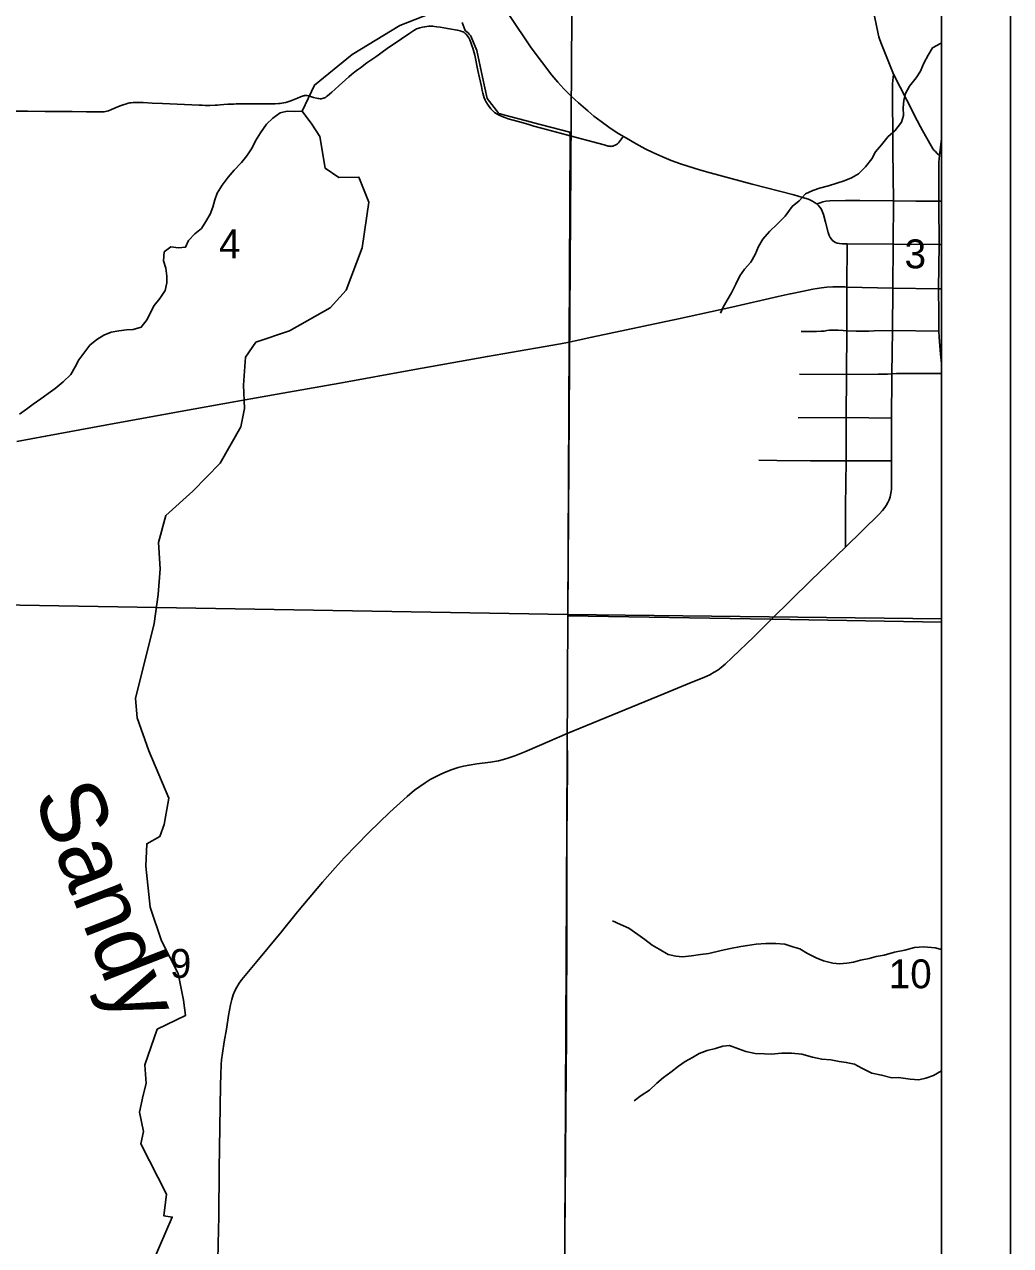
# Model space of a CAD drawing. Extents: x -8.8 to 41.4, y 0 to 34.6.
# Drawn here: x -3.204 to -1.774, y 16.599 to 18.37 of the extents above; entities that cross this region are included whole.
import ezdxf

# ---------------------------------------------------------------- set-up
doc = ezdxf.new("R2010")
doc.units = 0
for name, color, linetype in [('GM_X_City_Street', 7, 'Continuous'), ('GM_X_Corporation', 7, 'Continuous'), ('GM_X_County_Road', 7, 'Continuous'), ('GM_X_Minor_River', 7, 'Continuous'), ('GM_X_Minor_River_Text', 7, 'Continuous'), ('GM_X_State_Route', 7, 'Continuous'), ('GM_X_Township_Road', 7, 'Continuous'), ('GM_X_Township_Text', 7, 'Continuous'), ('SH_Border', 7, 'Continuous')]:
    doc.layers.add(name, color=color, linetype=linetype)

msp = doc.modelspace()

# ---------------------------------------------------------------- linework, layer by layer
at = {"layer": 'GM_X_City_Street'}
for p, q in [((-1.878, 18.0513), (-1.8743, 18.0512)), ((-1.9457, 17.9263), (-1.8782, 17.9255))]:
    msp.add_line(p, q, dxfattribs=at)
for points in [[(-1.8773, 18.1802), (-1.881, 18.1837), (-1.8833, 18.1858), (-1.8854, 18.1881), (-1.8876, 18.191), (-1.8895, 18.194), (-1.902, 18.2163), (-1.9048, 18.2218), (-1.9098, 18.2311), (-1.9245, 18.2605), (-1.9441, 18.298)], [(-2.0551, 18.11), (-2.0517, 18.1112), (-2.0489, 18.1122), (-2.0465, 18.1129), (-2.0422, 18.1137), (-2.0366, 18.1143), (-2.0138, 18.1148), (-1.9928, 18.1151), (-1.9442, 18.1144)], [(-1.9442, 18.1144), (-1.9115, 18.114), (-1.8784, 18.1138), (-1.8743, 18.1137)], [(-2.0136, 17.6123), (-2.0137, 17.6716), (-2.0129, 17.7375), (-2.0125, 17.8002), (-2.012, 17.8627), (-2.0117, 17.926), (-2.0117, 17.9894), (-2.0111, 18.0522)], [(-2.0779, 17.9249), (-2.0556, 17.9251), (-2.0488, 17.9252), (-2.0445, 17.9256), (-2.0408, 17.9261), (-2.0369, 17.9267), (-2.0323, 17.927), (-2.0242, 17.9267), (-2.0169, 17.9263), (-2.0117, 17.926), (-1.9983, 17.9253), (-1.9865, 17.9252), (-1.9797, 17.9254), (-1.9723, 17.9258), (-1.9457, 17.9263)], [(-2.0802, 17.8631), (-2.012, 17.8627), (-1.9662, 17.863), (-1.9526, 17.8632), (-1.9464, 17.8636)], [(-1.9464, 17.8636), (-1.9397, 17.8641), (-1.9302, 17.8642), (-1.8743, 17.8638)], [(-2.0824, 17.7998), (-2.0125, 17.8002), (-1.947, 17.7993)], [(-2.1395, 17.7383), (-2.1134, 17.7377), (-2.0644, 17.7374), (-2.0129, 17.7375), (-1.9469, 17.7373)]]:
    msp.add_lwpolyline(points, dxfattribs=at)
at = {"layer": 'GM_X_Corporation'}
for points in [[(-5.4008, 18.6369), (-5.4129, 17.3836), (-5.4212, 16.5483), (-5.4282, 16.3507), (-5.435, 15.3164), (-5.4368, 15.0446), (-5.4404, 14.5882), (-5.4429, 14.2618), (-5.4432, 14.2265), (-5.4442, 14.1), (-1.8743, 14.1), (-1.8743, 18.5906)], [(-2.5697, 18.3731), (-2.565, 18.3613), (-2.5643, 18.3608), (-2.564, 18.3606), (-2.561, 18.3581), (-2.5608, 18.3579), (-2.5592, 18.3561), (-2.5578, 18.3545), (-2.5576, 18.3542), (-2.5563, 18.3522), (-2.5484, 18.3325), (-2.5399, 18.2938), (-2.5331, 18.2626), (-2.5162, 18.241), (-2.5002, 18.2367), (-2.4874, 18.2334), (-2.469, 18.2285), (-2.4674, 18.2281), (-2.4134, 18.2139), (-2.4131, 18.2093), (-2.4144, 17.9101), (-2.4164, 17.5126), (-2.1219, 17.5076), (-1.8743, 17.5032), (-1.8743, 18.5904)]]:
    msp.add_lwpolyline(points, dxfattribs=at)
for points in [[(-3.3893, 18.614), (-2.4092, 18.5999), (-2.4162, 17.5144), (-3.4102, 17.5315)], [(-1.8743, 17.5082), (-1.8743, 18.5922), (-2.4092, 18.5999), (-2.4162, 17.5144)], [(-2.4162, 17.5144), (-2.421, 16.5107), (-3.4233, 16.5283), (-3.4102, 17.5315)], [(-1.8743, 16.504), (-1.8743, 17.5082), (-2.4162, 17.5144), (-2.421, 16.5107)]]:
    msp.add_lwpolyline(points, close=True, dxfattribs=at)
at = {"layer": 'GM_X_County_Road'}
for p, q in [((-1.8773, 18.1802), (-1.8743, 18.2044)), ((-1.878, 18.0513), (-1.8784, 18.1098))]:
    msp.add_line(p, q, dxfattribs=at)
msp.add_lwpolyline([(-1.8784, 18.1098), (-1.8784, 18.1138), (-1.8782, 18.1706), (-1.8778, 18.1755), (-1.8773, 18.1802)], dxfattribs=at)
at = {"layer": 'GM_X_Minor_River'}
for points in [[(-3.027, 16.5553), (-2.9899, 16.6404), (-3.0023, 16.6424), (-2.9985, 16.6738), (-3.0354, 16.7467), (-3.0317, 16.7645), (-3.0372, 16.7924), (-3.0321, 16.8174), (-3.0278, 16.834), (-3.0295, 16.8614), (-3.0117, 16.9129), (-2.9709, 16.9328), (-2.9735, 16.955), (-2.9816, 16.9937), (-3.0057, 17.041), (-3.0222, 17.0899), (-3.0281, 17.1495), (-3.0269, 17.1818), (-3.008, 17.1922), (-3.0017, 17.2098), (-2.995, 17.248), (-3.0241, 17.3169), (-3.0406, 17.3646), (-3.0434, 17.3925), (-3.0164, 17.5016), (-3.0104, 17.5436), (-3.0076, 17.5808), (-3.01, 17.6189), (-2.9992, 17.6578), (-2.9601, 17.6933), (-2.9203, 17.7341), (-2.8904, 17.7867), (-2.8853, 17.8131), (-2.8868, 17.847), (-2.8839, 17.8877), (-2.8687, 17.9092), (-2.82, 17.9257), (-2.7608, 17.959), (-2.7379, 17.9848), (-2.7146, 18.046), (-2.705, 18.1126), (-2.7193, 18.1485), (-2.7485, 18.1481), (-2.7681, 18.1617), (-2.776, 18.2077), (-2.7875, 18.2256), (-2.8016, 18.2444), (-2.7836, 18.2822), (-2.729, 18.3267), (-2.66, 18.3687), (-2.6043, 18.3903)], [(-1.8743, 18.3434), (-1.8758, 18.3428), (-1.8873, 18.3362), (-1.894, 18.3257), (-1.8999, 18.314), (-1.905, 18.3027), (-1.9113, 18.2926), (-1.921, 18.2807), (-1.9265, 18.2702), (-1.9293, 18.26), (-1.9299, 18.2494), (-1.9297, 18.2384), (-1.9326, 18.2286), (-1.9423, 18.2158), (-1.9519, 18.2077), (-1.9613, 18.1957), (-1.9702, 18.1853), (-1.9757, 18.1751), (-1.9846, 18.1635), (-1.9947, 18.1535), (-2.005, 18.1476), (-2.0157, 18.1436), (-2.0264, 18.14), (-2.0382, 18.1361), (-2.0512, 18.1329), (-2.0611, 18.1293), (-2.0715, 18.1246), (-2.0808, 18.1145), (-2.0912, 18.106), (-2.1013, 18.0921), (-2.1129, 18.0806), (-2.1237, 18.0698)], [(-2.8016, 18.2444), (-2.8129, 18.2441), (-2.8232, 18.2443), (-2.8335, 18.2419), (-2.8439, 18.2341), (-2.8535, 18.2255), (-2.8621, 18.2132), (-2.8691, 18.2012), (-2.8742, 18.1914), (-2.8817, 18.1798), (-2.8894, 18.1701), (-2.9003, 18.1589), (-2.9088, 18.1488), (-2.9177, 18.1372), (-2.9248, 18.1256), (-2.9284, 18.1158), (-2.9312, 18.1053), (-2.9352, 18.0951), (-2.9411, 18.0842), (-2.9477, 18.0741), (-2.9573, 18.0667), (-2.9663, 18.057), (-2.9706, 18.0472), (-2.9809, 18.0463), (-2.9918, 18.0476), (-3.0018, 18.0402), (-3.0025, 18.0273), (-2.9992, 18.0167), (-2.9976, 18.0053), (-2.9977, 17.9954), (-3.0002, 17.9844), (-3.008, 17.9728), (-3.0162, 17.9624), (-3.0213, 17.9526), (-3.0264, 17.9421), (-3.035, 17.9312), (-3.0464, 17.928), (-3.0563, 17.9271), (-3.0673, 17.9258), (-3.0787, 17.9237), (-3.0891, 17.9197), (-3.0994, 17.9131), (-3.1094, 17.905), (-3.1168, 17.8952), (-3.1254, 17.8836), (-3.1309, 17.8735), (-3.1368, 17.8626), (-3.148, 17.8518), (-3.1595, 17.8422), (-3.1699, 17.8348), (-3.1807, 17.827), (-3.1918, 17.8193), (-3.2014, 17.8123), (-3.2115, 17.8049)], [(-2.1237, 18.0698), (-2.1334, 18.0586), (-2.1397, 18.0481), (-2.1448, 18.0365), (-2.1511, 18.0252), (-2.16, 18.0155), (-2.167, 18.0058), (-2.1729, 17.9937), (-2.1792, 17.981), (-2.1855, 17.9705), (-2.191, 17.9603), (-2.1949, 17.9517)], [(-1.8743, 17.0284), (-1.8835, 17.0311), (-1.9002, 17.0322), (-1.9135, 17.0314), (-1.9276, 17.0276), (-1.9425, 17.0245), (-1.9578, 17.0204), (-1.9692, 17.0184), (-1.9795, 17.0156), (-1.9921, 17.0129), (-2.002, 17.0101), (-2.0119, 17.0088), (-2.0222, 17.0075), (-2.032, 17.0085), (-2.0456, 17.0119), (-2.0561, 17.0163), (-2.0688, 17.0227), (-2.08, 17.0294), (-2.0898, 17.0323), (-2.1015, 17.0364), (-2.1147, 17.0371), (-2.1292, 17.0371), (-2.1432, 17.0363), (-2.1558, 17.0343), (-2.1653, 17.033), (-2.1802, 17.03), (-2.1939, 17.0269), (-2.2118, 17.0228), (-2.224, 17.0212), (-2.2369, 17.0192), (-2.2499, 17.018), (-2.2597, 17.0187), (-2.2707, 17.0212), (-2.2837, 17.0291), (-2.2938, 17.035), (-2.3046, 17.0429), (-2.3147, 17.0503), (-2.3277, 17.0594), (-2.3401, 17.065), (-2.3514, 17.0702)], [(-1.8743, 16.8529), (-1.8747, 16.8526), (-1.8862, 16.8457), (-1.8973, 16.8418), (-1.9073, 16.8397), (-1.9201, 16.8404), (-1.9368, 16.8427), (-1.9463, 16.8426), (-1.9613, 16.8464), (-1.9753, 16.8494), (-1.9899, 16.8565), (-2.0008, 16.8621), (-2.0125, 16.8647), (-2.0227, 16.8661), (-2.0347, 16.8683), (-2.048, 16.8693), (-2.0616, 16.8723), (-2.077, 16.8765), (-2.0918, 16.878), (-2.1058, 16.878), (-2.1214, 16.8768), (-2.1309, 16.8771), (-2.1449, 16.8778), (-2.1581, 16.8804), (-2.1686, 16.8844), (-2.1818, 16.8893), (-2.1917, 16.8884), (-2.202, 16.8849), (-2.2142, 16.8818), (-2.2257, 16.8775), (-2.2357, 16.872), (-2.2461, 16.8659), (-2.2557, 16.8593), (-2.2669, 16.8508), (-2.2777, 16.8431), (-2.2874, 16.8346), (-2.2979, 16.8243), (-2.3099, 16.817), (-2.3199, 16.8089)]]:
    msp.add_lwpolyline(points, dxfattribs=at)
at = {"layer": 'GM_X_State_Route'}
for p, q in [((-1.9445, 18.0517), (-1.878, 18.0513)), ((-1.9451, 17.9877), (-1.8787, 17.9869)), ((-1.8787, 17.9869), (-1.8743, 17.9868)), ((-2.4142, 17.9096), (-2.4055, 17.9114)), ((-2.1257, 17.503), (-2.1214, 17.5073))]:
    msp.add_line(p, q, dxfattribs=at)
for points in [[(-1.9445, 18.0517), (-1.9442, 18.1144), (-1.9448, 18.1873), (-1.9453, 18.2838), (-1.9449, 18.2892), (-1.9446, 18.2932), (-1.9441, 18.298), (-1.9615, 18.3416), (-1.9638, 18.3477), (-1.9651, 18.3521), (-1.9661, 18.3564), (-1.9715, 18.3821), (-2.0065, 18.5779)], [(-2.5011, 18.383), (-2.4697, 18.3362), (-2.4397, 18.2967), (-2.4308, 18.2864), (-2.4219, 18.2769), (-2.4114, 18.2664), (-2.401, 18.2567), (-2.3875, 18.2448), (-2.3784, 18.2373), (-2.3681, 18.2293), (-2.357, 18.2214), (-2.3446, 18.2132), (-2.3358, 18.2078), (-2.3314, 18.2051), (-2.3174, 18.197), (-2.3043, 18.19), (-2.2932, 18.1845), (-2.2802, 18.1787), (-2.2664, 18.173), (-2.253, 18.168), (-2.2425, 18.1645), (-2.2252, 18.1593), (-2.2098, 18.1551)], [(-2.2098, 18.1551), (-2.1491, 18.1387), (-2.0884, 18.123), (-2.0758, 18.1193), (-2.0675, 18.1166), (-2.0645, 18.1154), (-2.0617, 18.1141), (-2.0585, 18.1122), (-2.0551, 18.11), (-2.0533, 18.1083), (-2.0508, 18.1054), (-2.049, 18.1026), (-2.0474, 18.0992), (-2.0458, 18.0945), (-2.0428, 18.0836), (-2.0389, 18.0687), (-2.0372, 18.0642), (-2.0357, 18.0612), (-2.0342, 18.0589), (-2.033, 18.0574)], [(-2.033, 18.0574), (-2.0324, 18.0567), (-2.0305, 18.0552), (-2.0284, 18.054), (-2.0257, 18.0529), (-2.0225, 18.0524), (-2.0187, 18.0522), (-2.0111, 18.0522), (-1.9445, 18.0517)], [(-1.9464, 17.8586), (-1.9464, 17.8636), (-1.9457, 17.9263), (-1.9451, 17.9877), (-1.9445, 18.0517)], [(-1.878, 18.0513), (-1.8787, 17.9869), (-1.8785, 17.9508), (-1.8784, 17.9359), (-1.8784, 17.9304), (-1.8782, 17.9255), (-1.8778, 17.9168)], [(-2.4055, 17.9114), (-2.3814, 17.9165), (-2.2556, 17.9433), (-2.1786, 17.9602), (-2.1113, 17.9755), (-2.0941, 17.9793)], [(-2.0941, 17.9793), (-2.0932, 17.9795), (-2.0744, 17.9836), (-2.061, 17.9862), (-2.0486, 17.9881), (-2.0408, 17.989), (-2.0321, 17.9896), (-2.0221, 17.9896), (-2.0148, 17.9895)], [(-2.0148, 17.9895), (-2.0117, 17.9894), (-1.9451, 17.9877)], [(-3.2151, 17.7654), (-3.1735, 17.7729), (-3.0874, 17.7888), (-2.9787, 17.8087), (-2.8975, 17.8233), (-2.8216, 17.8368), (-2.747, 17.8501), (-2.6412, 17.8691), (-2.533, 17.8887), (-2.5104, 17.8926), (-2.4271, 17.9072), (-2.4142, 17.9096)], [(-1.8778, 17.9168), (-1.8759, 17.892), (-1.8743, 17.8787)], [(-1.9469, 17.7793), (-1.947, 17.7993), (-1.9464, 17.8586)], [(-2.1214, 17.5073), (-2.0637, 17.5638), (-2.0136, 17.6123), (-1.965, 17.66), (-1.9602, 17.6653), (-1.9568, 17.6695), (-1.9546, 17.6726), (-1.9521, 17.6769), (-1.9503, 17.6809), (-1.9489, 17.6851), (-1.9477, 17.6904), (-1.9472, 17.6959), (-1.9468, 17.7052), (-1.9468, 17.7145), (-1.9469, 17.7373), (-1.9469, 17.7793)], [(-2.9237, 16.578), (-2.9234, 16.601), (-2.9226, 16.6419), (-2.9217, 16.7101), (-2.92, 16.8312), (-2.9197, 16.8473), (-2.919, 16.8616), (-2.9184, 16.8684), (-2.9172, 16.8783), (-2.9146, 16.8948), (-2.9115, 16.9132), (-2.9082, 16.9328), (-2.9055, 16.9481), (-2.9037, 16.956), (-2.9017, 16.9626), (-2.8993, 16.9684), (-2.8964, 16.974), (-2.8928, 16.9796), (-2.889, 16.9849), (-2.8673, 17.0113), (-2.832, 17.0538), (-2.8082, 17.0833), (-2.7723, 17.1262), (-2.7537, 17.1471), (-2.7406, 17.1613), (-2.7048, 17.1984), (-2.6745, 17.2279), (-2.6495, 17.2504), (-2.6385, 17.2595), (-2.631, 17.2651), (-2.6233, 17.2704), (-2.6158, 17.275), (-2.6082, 17.2792), (-2.6003, 17.283), (-2.5928, 17.2862), (-2.5841, 17.2895), (-2.5751, 17.2924), (-2.5676, 17.2943), (-2.5594, 17.2959), (-2.5482, 17.2976), (-2.5285, 17.3004), (-2.5169, 17.3024), (-2.5097, 17.304), (-2.502, 17.3063), (-2.4933, 17.3094), (-2.4789, 17.3152), (-2.4572, 17.3244), (-2.4171, 17.3417), (-2.2771, 17.3994), (-2.2374, 17.4156), (-2.219, 17.4232), (-2.2106, 17.4271), (-2.2041, 17.4306), (-2.1989, 17.4339), (-2.1939, 17.4375), (-2.1883, 17.4422), (-2.1778, 17.4519), (-2.1467, 17.4822), (-2.1257, 17.503)]]:
    msp.add_lwpolyline(points, dxfattribs=at)
at = {"layer": 'GM_X_Township_Road'}
for points in [[(-3.2402, 18.2446), (-3.1998, 18.2443), (-3.174, 18.2441), (-3.1531, 18.244), (-3.135, 18.2438), (-3.1143, 18.2436), (-3.1025, 18.2435), (-3.0935, 18.2434), (-3.091, 18.2435), (-3.0885, 18.2436), (-3.0869, 18.2438), (-3.0846, 18.2443), (-3.0822, 18.2451), (-3.0781, 18.2467), (-3.0681, 18.251), (-3.064, 18.2525), (-3.0595, 18.2542), (-3.0565, 18.2552), (-3.054, 18.2559), (-3.0518, 18.2563), (-3.0493, 18.2567), (-3.0466, 18.257), (-3.0439, 18.2571), (-3.0406, 18.2572), (-3.0319, 18.2568), (-3.0189, 18.2561), (-3.004, 18.2554), (-2.983, 18.2546), (-2.9507, 18.2532), (-2.9466, 18.2531), (-2.9424, 18.2529), (-2.9387, 18.2529), (-2.9354, 18.2529), (-2.9278, 18.2532), (-2.9242, 18.2533), (-2.9207, 18.2535), (-2.9151, 18.254), (-2.9092, 18.2544), (-2.9054, 18.2546), (-2.9007, 18.2548), (-2.8973, 18.2549), (-2.8918, 18.255), (-2.8872, 18.2551), (-2.8748, 18.2553), (-2.8514, 18.2551), (-2.8406, 18.2553), (-2.8358, 18.2555), (-2.8334, 18.2557), (-2.8312, 18.256), (-2.8286, 18.2564), (-2.8254, 18.2572), (-2.8225, 18.258), (-2.8195, 18.2589), (-2.8157, 18.2603), (-2.8081, 18.2633), (-2.804, 18.265), (-2.8011, 18.2661), (-2.8001, 18.2665), (-2.799, 18.2668), (-2.7982, 18.267), (-2.7973, 18.2672), (-2.7965, 18.2673), (-2.7957, 18.2673), (-2.7951, 18.2673), (-2.7944, 18.2671), (-2.7923, 18.2666), (-2.7897, 18.2658), (-2.7851, 18.2645), (-2.781, 18.2634), (-2.7786, 18.2628), (-2.7772, 18.2626), (-2.7753, 18.2625), (-2.7739, 18.2625), (-2.7724, 18.2627), (-2.7708, 18.2632), (-2.7693, 18.2637), (-2.7679, 18.2644), (-2.7664, 18.2655), (-2.7648, 18.2667), (-2.7618, 18.2693), (-2.7585, 18.272), (-2.7542, 18.276), (-2.7481, 18.2816), (-2.7388, 18.2901), (-2.734, 18.2943), (-2.7299, 18.2975), (-2.7252, 18.3013), (-2.7212, 18.3043), (-2.7171, 18.3074), (-2.7076, 18.3144), (-2.6949, 18.3233), (-2.6781, 18.3351), (-2.6577, 18.3492), (-2.6452, 18.3577), (-2.6395, 18.3615), (-2.6374, 18.3628), (-2.6358, 18.3637), (-2.6339, 18.3645), (-2.6308, 18.3654), (-2.6269, 18.3664), (-2.6237, 18.367), (-2.6207, 18.3674), (-2.6178, 18.3676), (-2.6151, 18.3676), (-2.6122, 18.3675), (-2.6097, 18.3673), (-2.6061, 18.367), (-2.6016, 18.3663), (-2.5959, 18.3653), (-2.5878, 18.3639), (-2.5766, 18.362), (-2.5744, 18.3615), (-2.5723, 18.3609), (-2.5701, 18.3601), (-2.5682, 18.3593), (-2.5665, 18.3584), (-2.565, 18.3573), (-2.5635, 18.3559), (-2.5622, 18.3541)], [(-2.4131, 18.2088), (-2.4181, 18.2102), (-2.4546, 18.22), (-2.4655, 18.2229), (-2.4745, 18.2255), (-2.4863, 18.2288), (-2.4954, 18.2314), (-2.5026, 18.2335), (-2.5077, 18.2353), (-2.5117, 18.2368), (-2.5151, 18.2382), (-2.5176, 18.2394), (-2.5203, 18.2409), (-2.5225, 18.2425), (-2.5247, 18.2443), (-2.5267, 18.2464), (-2.528, 18.2479), (-2.5306, 18.2513), (-2.533, 18.2548), (-2.5352, 18.2587), (-2.5361, 18.2605), (-2.5374, 18.2636), (-2.5385, 18.2671), (-2.5394, 18.2706), (-2.5403, 18.2743), (-2.5415, 18.28), (-2.543, 18.2866), (-2.5443, 18.2928), (-2.5466, 18.3036), (-2.5513, 18.3259), (-2.5541, 18.3356), (-2.5554, 18.3399), (-2.557, 18.3441), (-2.5586, 18.348), (-2.56, 18.3506), (-2.5622, 18.3541)], [(-2.3358, 18.2078), (-2.3371, 18.2061), (-2.3412, 18.2003), (-2.3429, 18.1985), (-2.3442, 18.1972), (-2.3458, 18.1962), (-2.3476, 18.1952), (-2.349, 18.1945), (-2.3507, 18.1938), (-2.3524, 18.1935), (-2.3536, 18.1934), (-2.3547, 18.1935), (-2.3559, 18.1936), (-2.3576, 18.1939), (-2.3638, 18.1955), (-2.3727, 18.1979), (-2.4131, 18.2088)], [(-2.4218, 16.5093), (-2.4201, 16.6656), (-2.4191, 16.7948), (-2.4182, 16.904), (-2.4181, 16.9674), (-2.418, 17.014), (-2.4176, 17.1891), (-2.4168, 17.2928), (-2.4171, 17.3417)]]:
    msp.add_lwpolyline(points, dxfattribs=at)
at = {"layer": 'SH_Border'}
for p, q in [((-1.7743, 21), (-1.7743, 14)), ((-1.8743, 20.9), (-1.8743, 14.1))]:
    msp.add_line(p, q, dxfattribs=at)

# ---------------------------------------------------------------- texts
at = {"layer": 'GM_X_Minor_River_Text'}
msp.add_text('Sandy', height=0.09467, rotation=291.2218, dxfattribs=at).set_placement((-3.1917, 17.2507))
at = {"layer": 'GM_X_Township_Text'}
for s, height, p in [('4', 0.0419, (-2.9222, 18.031)), ('3', 0.0419, (-1.928, 18.0165)), ('9', 0.0419, (-2.9934, 16.9873)), ('10', 0.04186, (-1.9509, 16.9723))]:
    msp.add_text(s, height=height, rotation=0, dxfattribs=at).set_placement(p)

doc.saveas('drawing.dxf')
